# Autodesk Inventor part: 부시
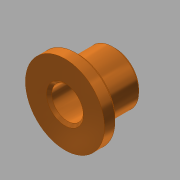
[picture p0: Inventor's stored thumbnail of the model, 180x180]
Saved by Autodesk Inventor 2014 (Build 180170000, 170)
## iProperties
Created: 2016-02
Part Number: 부시
Material: 스테인리스강
Document SubType Name: Modeling
Designer: mduedu
Density: 8.08 g/cm^3
Appearance: Metal 1600F Hot
Mass: 45.9536 g
Surface Area: 31.3929 cm^2
Volume: 5.68733 cm^3
Author: mduedu
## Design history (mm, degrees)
sketch "스케치1"
  geometry: C1 r 15 at (0, 0); 1 further point
  constraints: 1 centre point, 1 coincident
  dimensions: "d0" = 30 diameter of C1
extrude "돌출1" new body sketch "스케치1" distance "d1" = 5; taper "d2" = 0 deg
sketch "스케치2"
  geometry: C1 r 10 at (0, 0); 1 further point
  constraints: 1 centre point, 1 coincident
  dimensions: "d3" = 20 diameter of C1
extrude "돌출2" join sketch "스케치2" distance "d4" = 14; taper "d5" = 0 deg
hole "구멍1" diameter "d8" = 12; stored, may be unused: countersink angle "d12" = 90 deg, drill point angle "d14" = 118 deg; dims "d9" = 6, "d10" = 4, "d11" = 2, "d13" = 8, "d15" = 10, "d16" = 10
chamfer "모따기1" distance "d17" = 1; stored, may be unused: second distance "d18" = 2, angle "d19" = 45 deg
chamfer "모따기2" distance "d20" = 1; stored, may be unused: second distance "d21" = 2, angle "d22" = 45 deg
chamfer "모따기3" distance "d23" = 1; stored, may be unused: second distance "d24" = 2, angle "d25" = 45 deg
node "솔리드1"
